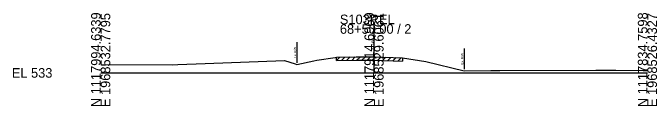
# Model space of a CAD drawing. Extents: x -26 to 163, y -10 to 24518.
# Drawn here: x -25.7 to 162.8, y 16990.3 to 17017.5 of the extents above; entities that cross this region are included whole.
import ezdxf

# ---------------------------------------------------------------- set-up
doc = ezdxf.new("R2010")
doc.units = 0
for name, color, linetype in [('RD_GPK_XS_Cell', 7, 'Continuous'), ('RD_XS_ExGround', 7, 'Continuous'), ('RD_XS_ExPaveRet', 7, 'Continuous'), ('RD_XS_ExRW', 7, 'Continuous'), ('RD_XS_TX_Elev_EX', 7, 'Continuous')]:
    doc.layers.add(name, color=color, linetype=linetype)

msp = doc.modelspace()

# ---------------------------------------------------------------- linework, layer by layer
at = {"layer": 'RD_GPK_XS_Cell'}
for p, q in [((80, 17000), (80, 17014.23)), ((0, 17000), (80, 17000)), ((80, 17000), (160, 17000))]:
    msp.add_line(p, q, dxfattribs=at)
at = {"layer": 'RD_XS_ExGround'}
msp.add_lwpolyline([(0, 17002.45), (21.11, 17002.4), (22.61, 17002.46), (30.6, 17002.76), (53.84, 17003.63), (56.94, 17002.63), (57.45, 17002.48), (62.41, 17003.54), (63.23, 17003.71), (68.62, 17004.53), (68.97, 17004.58), (74.8, 17004.68), (78.41, 17004.74), (80, 17004.69), (88.37, 17004.41), (95.11, 17003.32), (106.36, 17000.64), (114.19, 17000.7), (116.83, 17000.7), (144.92, 17000.79), (150.74, 17000.78), (158.78, 17000.7), (160, 17000.69)], dxfattribs=at)
at = {"layer": 'RD_XS_ExPaveRet'}
for p, q in [((68.97, 17003.58), (69.99, 17004.6)), ((68.97, 17003.58), (68.97, 17004.58)), ((70.47, 17003.61), (71.49, 17004.62)), ((71.97, 17003.63), (72.99, 17004.65)), ((73.47, 17003.66), (74.49, 17004.67)), ((74.97, 17003.68), (75.99, 17004.7)), ((76.47, 17003.71), (77.49, 17004.73)), ((77.97, 17003.74), (78.96, 17004.72)), ((79.47, 17003.71), (80.44, 17004.68)), ((80.97, 17003.66), (81.94, 17004.63)), ((82.47, 17003.61), (83.44, 17004.58)), ((83.97, 17003.56), (84.94, 17004.53)), ((85.47, 17003.51), (86.44, 17004.48)), ((86.97, 17003.46), (87.94, 17004.43)), ((88.37, 17004.41), (88.37, 17003.41)), ((68.97, 17003.58), (74.8, 17003.68)), ((74.8, 17003.68), (78.41, 17003.74)), ((78.41, 17003.74), (80, 17003.69)), ((80, 17003.69), (88.37, 17003.41))]:
    msp.add_line(p, q, dxfattribs=at)
at = {"layer": 'RD_XS_ExRW'}
for p, q in [((57.45, 17008.98), (57.45, 17002.98)), ((106.36, 17007.14), (106.36, 17001.14))]:
    msp.add_line(p, q, dxfattribs=at)

# ---------------------------------------------------------------- texts
at = {"layer": 'RD_GPK_XS_Cell'}
for s, p in [('N 1117994.6339', (0, 16990)), ('E 1968532.7795', (2.8, 16990)), ('N 1117914.6969', (80, 16990)), ('E 1968529.6061', (82.8, 16990)), ('N 1117834.7598', (160, 16990)), ('E 1968526.4327', (162.8, 16990))]:
    msp.add_text(s, height=2.8, rotation=90, dxfattribs=at).set_placement(p)
for s, p in [('S103REL', (70, 17014.23)), ('68+50.00 / 2', (70, 17011.43)), ('EL 533', (-26, 16998.6))]:
    msp.add_text(s, height=2.8, dxfattribs=at).set_placement(p)
at = {"layer": 'RD_XS_ExRW'}
for p in [(57.2, 17004.32), (106.11, 17002.48)]:
    msp.add_text('Ex. R/W ', height=0.65, rotation=90, dxfattribs=at).set_placement(p)
at = {"layer": 'RD_XS_TX_Elev_EX'}
msp.add_text('537.69', height=0.8, rotation=90, dxfattribs=at).set_placement((79.9, 17006.69))

doc.saveas('drawing.dxf')
